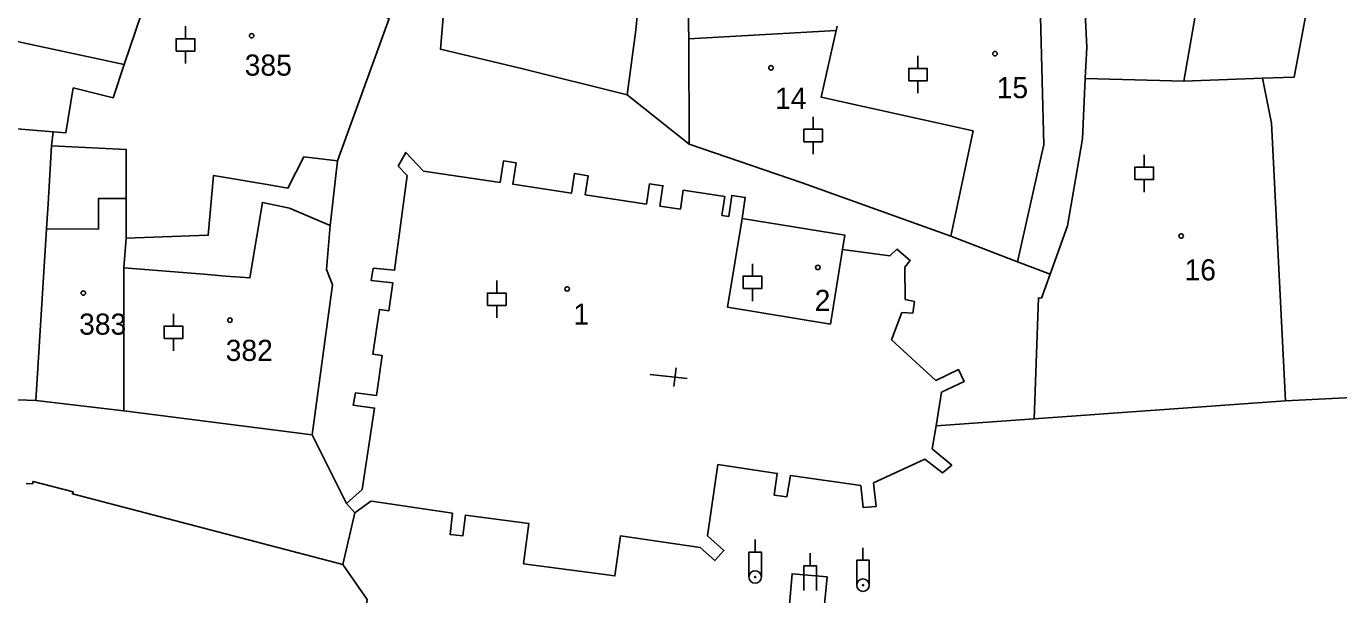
# Model space of a CAD drawing. Extents: x -737240 to -735272, y -1119606 to -1117878.
# Drawn here: x -736024.9 to -735919.3, y -1119489.3 to -1119443.6 of the extents above; entities that cross this region are included whole.
import ezdxf

# ---------------------------------------------------------------- set-up
doc = ezdxf.new("R2010")
doc.units = 0
for name, color, linetype in [('Level 1', 7, 'Continuous'), ('Level 19', 7, 'Continuous'), ('Level 25', 7, 'Continuous'), ('Level 4', 7, 'Continuous')]:
    doc.layers.add(name, color=color, linetype=linetype)

msp = doc.modelspace()

# ---------------------------------------------------------------- linework, layer by layer
at = {"layer": 'Level 1'}
for p, q in [((-736017.07, -1119446.68), (-736013.53, -1119436.23)), ((-735971.8, -1119436.87), (-735971.62, -1119444.62)), ((-735959.68, -1119443.6), (-735959.75, -1119443.95)), ((-736026.81, -1119444.6), (-736017.07, -1119446.68)), ((-735971.62, -1119444.62), (-735971.57, -1119453.09)), ((-735925.43, -1119447.78), (-735931.76, -1119448.02)), ((-735971.57, -1119453.09), (-735976.58, -1119449.13)), ((-736033.14, -1119451.24), (-736022.77, -1119452.11)), ((-736022.77, -1119452.11), (-736022.91, -1119453.22)), ((-736024.17, -1119473.71), (-736023.32, -1119459.89)), ((-736016.9, -1119460.65), (-736017.08, -1119463.04)), ((-735945.16, -1119462.55), (-735950.53, -1119460.49)), ((-736017.09, -1119474.54), (-736017.08, -1119463.04)), ((-735942.53, -1119463.56), (-735945.16, -1119462.55)), ((-736024.17, -1119473.71), (-736017.09, -1119474.54)), ((-735923.57, -1119473.73), (-735943.81, -1119475.19)), ((-735918.2, -1119473.46), (-735923.57, -1119473.73)), ((-736017.09, -1119474.54), (-736001.94, -1119476.47)), ((-735943.81, -1119475.19), (-735951.71, -1119475.76)), ((-736001.94, -1119476.47), (-735999.16, -1119481.99)), ((-735998.49, -1119482.76), (-735999.16, -1119481.99)), ((-735998.49, -1119482.76), (-735999.46, -1119486.92))]:
    msp.add_line(p, q, dxfattribs=at)
for points in [[(-735919.97, -1119432.2), (-735922.87, -1119447.69), (-735925.43, -1119447.78)], [(-735976.58, -1119449.13), (-735985.07, -1119446.99), (-735991.6, -1119445.45), (-735990.75, -1119435.16), (-735990.6, -1119435.18)], [(-736013.53, -1119436.23), (-735995.74, -1119442.97), (-735999.89, -1119454.43)], [(-735975.23, -1119437.12), (-735975.87, -1119443.93), (-735976.58, -1119449.13)], [(-735939.69, -1119447.8), (-735939.57, -1119445.28), (-735939.83, -1119439.75)], [(-735931.76, -1119448.02), (-735930.44, -1119440.46), (-735932.57, -1119440.3), (-735935.74, -1119440.06)], [(-735943.31, -1119442.84), (-735943.04, -1119453.14), (-735943.22, -1119453.94), (-735945.16, -1119462.55)], [(-735959.75, -1119443.95), (-735960.95, -1119449.31), (-735948.73, -1119452.02), (-735950.53, -1119460.49)], [(-735942.53, -1119463.56), (-735941.12, -1119459.67), (-735939.92, -1119452.66), (-735939.69, -1119447.8)], [(-735925.43, -1119447.78), (-735924.71, -1119451.4), (-735923.57, -1119473.73)], [(-736023.32, -1119459.89), (-736023.17, -1119457.88), (-736022.91, -1119453.22)], [(-736022.91, -1119453.22), (-736016.9, -1119453.52), (-736016.9, -1119457.47)], [(-735999.16, -1119481.99), (-735997.9, -1119480.87), (-735996.91, -1119474.32), (-735998.63, -1119474.08), (-735998.45, -1119473.1), (-735996.76, -1119473.32), (-735996.29, -1119470.1), (-735997.04, -1119469.99), (-735996.52, -1119466.39), (-735995.77, -1119466.5), (-735995.44, -1119464.24), (-735997.17, -1119464.06), (-735997.01, -1119463.08), (-735995.29, -1119463.24), (-735994.29, -1119455.61), (-735995, -1119454.87), (-735994.38, -1119453.75), (-735992.96, -1119455.25), (-735986.79, -1119456.17), (-735986.53, -1119454.44), (-735985.51, -1119454.59), (-735985.77, -1119456.32), (-735981.04, -1119457.02), (-735980.8, -1119455.44), (-735979.71, -1119455.65), (-735979.94, -1119457.18), (-735975.01, -1119457.91), (-735974.77, -1119456.29), (-735973.7, -1119456.43), (-735973.94, -1119458.07), (-735972.29, -1119458.32), (-735972.06, -1119456.8), (-735968.72, -1119457.29), (-735968.95, -1119458.82), (-735968.4, -1119458.9), (-735968.15, -1119457.22), (-735967.07, -1119457.38), (-735967.32, -1119459.06)], [(-735950.53, -1119460.49), (-735962.49, -1119456.21), (-735971.57, -1119453.09)], [(-735999.89, -1119454.43), (-736000.4, -1119458.93), (-736000.48, -1119459.64)], [(-736017.08, -1119463.04), (-736010.66, -1119463.56), (-736008.87, -1119463.71), (-736006.94, -1119463.85), (-736006.89, -1119463.52), (-736005.94, -1119457.78), (-736003.76, -1119458.23), (-736000.48, -1119459.64)], [(-736016.9, -1119457.47), (-736016.9, -1119459.97), (-736016.9, -1119460.65)], [(-735967.32, -1119459.06), (-735968.49, -1119466.21), (-735960.21, -1119467.57), (-735959.23, -1119461.57)], [(-735967.32, -1119459.06), (-735959.04, -1119460.42), (-735959.23, -1119461.57)], [(-736000.48, -1119459.64), (-736000.77, -1119463.18), (-736000.3, -1119464.4), (-736001.94, -1119476.47)], [(-735959.23, -1119461.57), (-735955.42, -1119462.08), (-735954.87, -1119461.55), (-735953.78, -1119462.46), (-735954.23, -1119463), (-735954.18, -1119465.58), (-735953.45, -1119465.75), (-735953.58, -1119466.7), (-735954.46, -1119466.64), (-735955.29, -1119468.83), (-735951.72, -1119472.1), (-735949.9, -1119471.23), (-735949.45, -1119472.18), (-735951.26, -1119473.05), (-735951.71, -1119475.76)], [(-735943.81, -1119475.19), (-735943.47, -1119465.46), (-735943.22, -1119465.48), (-735942.53, -1119463.56)], [(-736034.34, -1119473.29), (-736034.33, -1119473.53), (-736033.38, -1119473.55), (-736033.39, -1119474.07), (-736032.14, -1119474.17), (-736032.11, -1119473.43), (-736024.17, -1119473.71)], [(-735951.71, -1119475.76), (-735952.01, -1119477.59), (-735950.44, -1119478.92), (-735951.19, -1119479.54), (-735952.6, -1119478.43), (-735956.73, -1119480.34), (-735956.53, -1119482.23), (-735957.58, -1119482.32), (-735957.77, -1119480.56), (-735963.43, -1119479.74), (-735963.73, -1119481.47), (-735964.74, -1119481.32), (-735964.49, -1119479.58), (-735969.27, -1119478.87), (-735970.11, -1119484.61), (-735968.79, -1119485.77), (-735969.52, -1119486.59), (-735970.7, -1119485.55), (-735977.12, -1119484.61), (-735977.56, -1119487.83), (-735984.92, -1119486.85), (-735984.48, -1119483.62), (-735989.59, -1119482.93), (-735989.79, -1119484.59), (-735990.83, -1119484.5), (-735990.64, -1119482.79), (-735996.97, -1119481.84), (-735997.2, -1119481.81), (-735998.49, -1119482.76)], [(-735999.46, -1119486.92), (-736021.23, -1119481.23), (-736021.18, -1119481.06), (-736024.4, -1119480.22), (-736024.45, -1119480.41), (-736024.96, -1119480.39)], [(-735999.46, -1119486.92), (-735997.51, -1119489.73), (-735998.93, -1119500.22), (-735998.51, -1119500.28), (-735999.07, -1119504.42), (-735999.54, -1119504.35), (-735999.6, -1119504.61)]]:
    msp.add_lwpolyline(points, dxfattribs=at)
at = {"layer": 'Level 25'}
for p, q in [((-736012.13, -1119444.61), (-736012.13, -1119443.61)), ((-736012.13, -1119445.61), (-736012.13, -1119446.61)), ((-735953.16, -1119446.99), (-735953.16, -1119445.99)), ((-735953.16, -1119447.99), (-735953.16, -1119448.99)), ((-735961.59, -1119451.89), (-735961.59, -1119450.89)), ((-735961.59, -1119452.89), (-735961.59, -1119453.89)), ((-735934.95, -1119454.94), (-735934.95, -1119453.94)), ((-735934.95, -1119455.94), (-735934.95, -1119456.94)), ((-735966.49, -1119463.71), (-735966.49, -1119462.71)), ((-735987.07, -1119465.07), (-735987.07, -1119464.07)), ((-735966.49, -1119464.71), (-735966.49, -1119465.71)), ((-735987.07, -1119466.07), (-735987.07, -1119467.07)), ((-736013.1, -1119467.73), (-736013.1, -1119466.73)), ((-736013.1, -1119468.73), (-736013.1, -1119469.73)), ((-735974.71, -1119471.61), (-735971.73, -1119471.943)), ((-735972.807, -1119472.577), (-735972.64, -1119471.087)), ((-735966.27, -1119485.91), (-735966.27, -1119484.91)), ((-735961.84, -1119487.01), (-735961.84, -1119486.01)), ((-735957.59, -1119486.57), (-735957.59, -1119485.57))]:
    msp.add_line(p, q, dxfattribs=at)
for points in [[(-736012.88, -1119445.61), (-736011.38, -1119445.61), (-736011.38, -1119444.61), (-736012.88, -1119444.61)], [(-735953.91, -1119447.99), (-735952.41, -1119447.99), (-735952.41, -1119446.99), (-735953.91, -1119446.99)], [(-735962.34, -1119452.89), (-735960.84, -1119452.89), (-735960.84, -1119451.89), (-735962.34, -1119451.89)], [(-735935.7, -1119455.94), (-735934.2, -1119455.94), (-735934.2, -1119454.94), (-735935.7, -1119454.94)], [(-735967.24, -1119464.71), (-735965.74, -1119464.71), (-735965.74, -1119463.71), (-735967.24, -1119463.71)], [(-735987.82, -1119466.07), (-735986.32, -1119466.07), (-735986.32, -1119465.07), (-735987.82, -1119465.07)], [(-736013.85, -1119468.73), (-736012.35, -1119468.73), (-736012.35, -1119467.73), (-736013.85, -1119467.73)]]:
    msp.add_lwpolyline(points, close=True, dxfattribs=at)
for points in [[(-735966.77, -1119487.91), (-735966.77, -1119485.91), (-735965.77, -1119485.91), (-735965.77, -1119487.91)], [(-735958.09, -1119488.57), (-735958.09, -1119486.57), (-735957.09, -1119486.57), (-735957.09, -1119488.57)], [(-735962.34, -1119489.01), (-735962.34, -1119487.01), (-735961.34, -1119487.01), (-735961.34, -1119489.01)]]:
    msp.add_lwpolyline(points, dxfattribs=at)
for centre, radius in [((-735966.27, -1119487.91), 0.5), ((-735966.27, -1119487.91), 0.05), ((-735957.59, -1119488.57), 0.5), ((-735957.59, -1119488.57), 0.05)]:
    msp.add_circle(centre, radius, dxfattribs=at)
for centre in [(-736006.8, -1119444.37), (-735946.96, -1119445.81), (-735964.99, -1119446.95), (-735931.98, -1119460.48), (-735961.22, -1119463.01), (-736020.35, -1119465.07), (-735981.4, -1119464.74), (-736008.55, -1119467.25)]:
    msp.add_ellipse(centre, major_axis=(0.18, 0), ratio=0.9848078, dxfattribs=at)
at = {"layer": 'Level 4'}
msp.add_line((-735971.62, -1119444.62), (-735959.75, -1119443.95), dxfattribs=at)
for points in [[(-736022.77, -1119452.11), (-736021.77, -1119452.19), (-736021.16, -1119448.56), (-736017.96, -1119449.35), (-736017.07, -1119446.68)], [(-735939.69, -1119447.8), (-735934.7, -1119447.94), (-735931.76, -1119448.02)], [(-736016.9, -1119460.65), (-736010.29, -1119460.42), (-736009.87, -1119455.61), (-736005.7, -1119456.32), (-736003.88, -1119456.64), (-736002.59, -1119454.1), (-735999.89, -1119454.43)], [(-736023.32, -1119459.89), (-736019.14, -1119459.94), (-736019.14, -1119457.47), (-736016.9, -1119457.47)], [(-735960.48, -1119487.91), (-735960.74, -1119490.65), (-735963.52, -1119490.44), (-735963.3, -1119487.65), (-735960.48, -1119487.91)]]:
    msp.add_lwpolyline(points, dxfattribs=at)

# ---------------------------------------------------------------- texts
at = {"layer": 'Level 19'}
for s, p in [('385', (-736007.36, -1119447.58)), ('15', (-735946.825, -1119449.39)), ('14', (-735964.665, -1119450.25)), ('16', (-735931.705, -1119464.05)), ('2', (-735961.48, -1119466.51)), ('1', (-735980.9, -1119467.61)), ('383', (-736020.69, -1119468.42)), ('382', (-736008.89, -1119470.53))]:
    msp.add_text(s, height=1.7, dxfattribs=at).set_placement(p)

doc.saveas('drawing.dxf')
